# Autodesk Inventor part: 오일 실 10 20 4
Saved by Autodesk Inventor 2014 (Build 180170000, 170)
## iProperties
Created: 2024-05
Part Number: 오일 실 10 20 4
Material: 일반
Document SubType Name: Modeling
Designer: dg
Density: 1 g/cm^3
Appearance: 기본값
Author: dg
Author: jhkim
Description: 오일 실 - 비스프링, 조립 GA
Creation Date: 2024-05-07
Sending System: Autodesk Inventor 2025
Preprocessor: ST-DEVELOPER v20
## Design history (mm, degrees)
node "오일 실 10 20 41"
body "Solid1"
node "기준1"
